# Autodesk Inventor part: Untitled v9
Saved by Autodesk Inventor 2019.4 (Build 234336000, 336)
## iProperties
Created: 2020-01
Part Number: Untitled v9
Material: Generic
Document SubType Name: Modeling
Designer: Administrator
Density: 1 g/cm^3
Appearance: Default
Author: Administrator
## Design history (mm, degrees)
feature "Body1"
body "Solid1"
